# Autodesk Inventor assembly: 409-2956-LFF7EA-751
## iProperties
Created: 2010-06
Part Number: 409-2956-LFF7EA-751
Document SubType Name: Weldment
Designer: S. Boerckel
Mass: 5583.58 g
Surface Area: 1773.75 cm^2
Volume: 710.561 cm^3
Density: 7.85799 g/cm^3
Description: RECIRCULATION SPOOL
Weld Material: Welded Steel Mild
User Status: WELD
Material: WEDLMENT
SMR: =<MATERIAL>
Author: S. Boerckel
Revision Number: B
Subject: DEMIN WATER FORWARDING PUMP SKID-7EA
